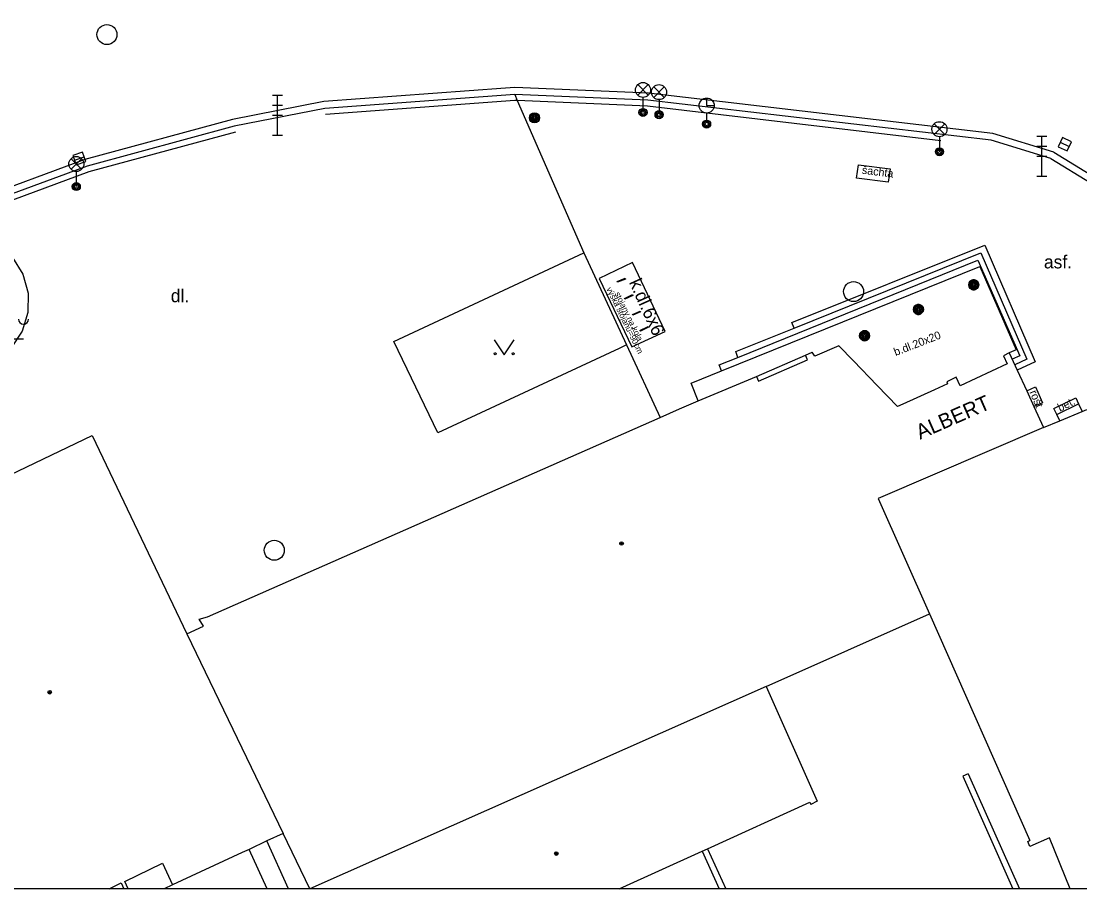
# Model space of a CAD drawing. Extents: x -600309 to -598967, y -1161267 to -1160292.
# Drawn here: x -599307.7 to -599254.8, y -1161267 to -1161223.7 of the extents above; entities that cross this region are included whole.
import ezdxf

# ---------------------------------------------------------------- set-up
doc = ezdxf.new("R2010")
doc.units = 0
for name, color, linetype in [('Level 10', 7, 'Continuous'), ('Level 11', 7, 'Continuous'), ('Level 24', 7, 'Continuous'), ('Level 25', 7, 'Continuous'), ('Level 26', 7, 'Continuous'), ('Level 27', 7, 'Continuous'), ('Level 33', 7, 'Continuous'), ('Level 36', 7, 'Continuous'), ('Level 39', 7, 'Continuous'), ('Level 40', 7, 'Continuous'), ('Level 41', 7, 'Continuous'), ('Level 42', 7, 'Continuous'), ('Level 5', 7, 'Continuous'), ('Level 6', 7, 'Continuous'), ('Level 7', 7, 'Continuous'), ('Level 9', 7, 'Continuous'), ('Vrstva 63', 7, 'Continuous')]:
    doc.layers.add(name, color=color, linetype=linetype)

msp = doc.modelspace()

# ---------------------------------------------------------------- linework, layer by layer
at = {"layer": 'Level 10'}
for points in [[(-599283.05, -1161227.35), (-599292.54, -1161228.05), (-599297.06, -1161228.94), (-599304.4099, -1161230.93), (-599309.89, -1161232.95), (-599324.35, -1161239.64)], [(-599256.27, -1161230.55), (-599259.24, -1161229.64), (-599276.4, -1161227.64), (-599283.05, -1161227.35)], [(-599256.27, -1161230.55), (-599254.25, -1161231.78), (-599252.45, -1161233.3), (-599250.9099, -1161235.09), (-599249.6599, -1161237.1)]]:
    msp.add_lwpolyline(points, dxfattribs=at)
at = {"layer": 'Level 11'}
msp.add_line((-599295.4188, -1161267.0314), (-599296.31, -1161265.06), dxfattribs=at)
for points in [[(-599256.11, -1161230.24), (-599259.17, -1161229.3), (-599276.37, -1161227.29), (-599283.05, -1161227), (-599283.5165, -1161227.0342), (-599292.59, -1161227.7), (-599297.14, -1161228.6), (-599304.52, -1161230.6), (-599310.02, -1161232.63), (-599324.5, -1161239.32), (-599330.9699, -1161242.33), (-599342.09, -1161247.58)], [(-599283.05, -1161227.35), (-599282.92, -1161227.6599)], [(-599282.92, -1161227.6599), (-599279.59, -1161235.27)], [(-599256.11, -1161230.24), (-599254.05, -1161231.5), (-599252.2, -1161233.06), (-599250.62, -1161234.89), (-599249.35, -1161236.94)], [(-599310.7, -1161234.25), (-599309.74, -1161234.4099), (-599308.86, -1161234.84), (-599308.13, -1161235.5), (-599307.62, -1161236.33), (-599307.36, -1161237.27), (-599307.37, -1161238.25), (-599307.6599, -1161239.18), (-599308.2, -1161240)], [(-599269.09, -1161239.02), (-599269.2, -1161238.74), (-599259.57, -1161234.88), (-599257.04, -1161240.71), (-599257.94, -1161241.12)], [(-599289.09, -1161239.69), (-599279.59, -1161235.27)], [(-599279.59, -1161235.27), (-599277.46, -1161239.86)], [(-599269.09, -1161239.02), (-599259.77, -1161235.26), (-599257.46, -1161240.58), (-599258.06, -1161240.86)], [(-599277.17, -1161235.75), (-599278.83, -1161236.54)], [(-599275.53, -1161239.19), (-599277.17, -1161235.75)], [(-599271.9099, -1161240.49), (-599259.9099, -1161235.63), (-599257.82, -1161240.4099), (-599258.19, -1161240.58)], [(-599278.83, -1161236.54), (-599277.19, -1161239.95)], [(-599277.19, -1161239.95), (-599275.53, -1161239.19)], [(-599271.9099, -1161240.49), (-599272, -1161240.19), (-599269.09, -1161239.02)], [(-599277.46, -1161239.86), (-599277.8346, -1161240.0344), (-599286.89, -1161244.25), (-599289.09, -1161239.69)], [(-599277.46, -1161239.86), (-599275.78, -1161243.48)], [(-599272.71, -1161241.1599), (-599272.84, -1161240.86), (-599271.9099, -1161240.49)], [(-599270.9699, -1161241.44), (-599268.52, -1161240.38)], [(-599257.4699, -1161242.15), (-599257.03, -1161241.95), (-599256.69, -1161242.75), (-599257.11, -1161242.94)], [(-599256.11, -1161243.04), (-599255.02, -1161242.51)], [(-599255.97, -1161243.33), (-599254.88, -1161242.8)], [(-599255.02, -1161242.51), (-599254.88, -1161242.8), (-599254.7, -1161243.18)], [(-599255.82, -1161243.65), (-599255.97, -1161243.33), (-599256.11, -1161243.04)], [(-599260.39, -1161261.29), (-599260.6599, -1161261.4099)]]:
    msp.add_lwpolyline(points, dxfattribs=at)
at = {"layer": 'Level 24'}
msp.add_line((-599307.59, -1161239.57), (-599308.09, -1161239.57), dxfattribs=at)
msp.add_arc((-599307.59, -1161238.57), 0.25, 180, 0, dxfattribs=at)
at = {"layer": 'Level 25'}
for points in [[(-599277.91, -1161236.73), (-599277.93, -1161236.69), (-599277.53, -1161236.53)], [(-599277.53, -1161236.53), (-599277.51, -1161236.57), (-599277.91, -1161236.73)], [(-599277.54, -1161237.58), (-599277.56, -1161237.54), (-599277.16, -1161237.35)], [(-599277.16, -1161237.35), (-599277.14, -1161237.39), (-599277.54, -1161237.58)], [(-599277.15, -1161238.38), (-599277.17, -1161238.34), (-599276.78, -1161238.17)], [(-599276.78, -1161238.17), (-599276.76, -1161238.21), (-599277.15, -1161238.38)], [(-599276.77, -1161239.18), (-599276.79, -1161239.14), (-599276.39, -1161238.94)], [(-599276.39, -1161238.94), (-599276.37, -1161238.98), (-599276.77, -1161239.18)]]:
    msp.add_lwpolyline(points, dxfattribs=at)
for centre, radius in [((-599282.06, -1161228.52), 0.25), ((-599282.06, -1161228.52), 0.2), ((-599282.06, -1161228.52), 0.15), ((-599282.06, -1161228.52), 0.1), ((-599282.06, -1161228.52), 0.05), ((-599260.12, -1161236.86), 0.25), ((-599260.12, -1161236.86), 0.2), ((-599260.12, -1161236.86), 0.15), ((-599260.12, -1161236.86), 0.1), ((-599260.12, -1161236.86), 0.05), ((-599262.88, -1161238.09), 0.25), ((-599262.88, -1161238.09), 0.2), ((-599262.88, -1161238.09), 0.15), ((-599262.88, -1161238.09), 0.1), ((-599262.88, -1161238.09), 0.05), ((-599265.57, -1161239.4), 0.25), ((-599265.57, -1161239.4), 0.2), ((-599265.57, -1161239.4), 0.15), ((-599265.57, -1161239.4), 0.1), ((-599265.57, -1161239.4), 0.05)]:
    msp.add_circle(centre, radius, dxfattribs=at)
at = {"layer": 'Level 26'}
msp.add_lwpolyline([(-599264.3, -1161231.07), (-599264.39, -1161231.74), (-599265.97, -1161231.54), (-599265.88, -1161230.87), (-599264.3, -1161231.07)], dxfattribs=at)
at = {"layer": 'Level 27'}
for p, q in [((-599255.7961, -1161229.7333), (-599255.3439, -1161229.9467)), ((-599305.0364, -1161230.6314), (-599304.5636, -1161230.4686))]:
    msp.add_line(p, q, dxfattribs=at)
for points in [[(-599255.9028, -1161229.9594), (-599255.4506, -1161230.1728), (-599255.2372, -1161229.7206), (-599255.6894, -1161229.5072)], [(-599304.955, -1161230.8678), (-599304.4822, -1161230.705), (-599304.645, -1161230.2322), (-599305.1178, -1161230.395)]]:
    msp.add_lwpolyline(points, close=True, dxfattribs=at)
for centre in [(-599303.42, -1161224.36), (-599266.12, -1161237.2), (-599295.06, -1161250.12)]:
    msp.add_circle(centre, 0.5, dxfattribs=at)
at = {"layer": 'Level 33'}
for p, q in [((-599276.905, -1161227.39), (-599276.375, -1161226.86)), ((-599276.905, -1161226.86), (-599276.375, -1161227.39)), ((-599276.105, -1161227.5), (-599275.575, -1161226.97)), ((-599276.105, -1161226.97), (-599275.575, -1161227.5)), ((-599295.15, -1161227.39), (-599294.65, -1161227.39)), ((-599294.9, -1161229.39), (-599294.9, -1161227.39)), ((-599276.64, -1161227.5), (-599276.64, -1161228.25)), ((-599295.15, -1161227.89), (-599294.65, -1161227.89)), ((-599275.84, -1161227.61), (-599275.84, -1161228.36)), ((-599295.15, -1161228.39), (-599294.65, -1161228.39)), ((-599273.46, -1161228.28), (-599273.46, -1161228.63)), ((-599262.095, -1161229.35), (-599261.565, -1161228.82)), ((-599262.095, -1161228.82), (-599261.565, -1161229.35)), ((-599295.15, -1161229.39), (-599294.65, -1161229.39)), ((-599261.83, -1161229.46), (-599261.83, -1161230.21)), ((-599256.96, -1161229.44), (-599256.46, -1161229.44)), ((-599256.71, -1161231.44), (-599256.71, -1161229.44)), ((-599256.96, -1161229.94), (-599256.46, -1161229.94)), ((-599305.215, -1161231.09), (-599304.685, -1161230.56)), ((-599305.215, -1161230.56), (-599304.685, -1161231.09)), ((-599256.96, -1161230.44), (-599256.46, -1161230.44)), ((-599304.95, -1161231.2), (-599304.95, -1161231.95)), ((-599256.96, -1161231.44), (-599256.46, -1161231.44))]:
    msp.add_line(p, q, dxfattribs=at)
msp.add_lwpolyline([(-599273.46, -1161227.53), (-599273.46, -1161227.905), (-599273.085, -1161227.905)], dxfattribs=at)
for centre, radius in [((-599276.64, -1161227.125), 0.375), ((-599275.84, -1161227.235), 0.375), ((-599273.46, -1161227.905), 0.375), ((-599276.64, -1161228.25), 0.2), ((-599276.64, -1161228.25), 0.1445), ((-599276.64, -1161228.25), 0.0876), ((-599275.84, -1161228.36), 0.2), ((-599275.84, -1161228.36), 0.1445), ((-599275.84, -1161228.36), 0.0876), ((-599273.46, -1161228.83), 0.2), ((-599273.46, -1161228.83), 0.1445), ((-599273.46, -1161228.83), 0.0876), ((-599261.83, -1161229.085), 0.375), ((-599261.83, -1161230.21), 0.2), ((-599261.83, -1161230.21), 0.1445), ((-599261.83, -1161230.21), 0.0876), ((-599304.95, -1161230.825), 0.375), ((-599304.95, -1161231.95), 0.2), ((-599304.95, -1161231.95), 0.1445), ((-599304.95, -1161231.95), 0.0876)]:
    msp.add_circle(centre, radius, dxfattribs=at)
at = {"layer": 'Level 36'}
msp.add_lwpolyline([(-599284.07, -1161239.6), (-599283.57, -1161240.35), (-599283.07, -1161239.6)], dxfattribs=at)
for centre in [(-599284.0202, -1161240.2998), (-599283.1208, -1161240.2998)]:
    msp.add_circle(centre, 0.05, dxfattribs=at)
at = {"layer": 'Level 39'}
for centre, radius in [((-599277.71, -1161249.78), 0.09), ((-599277.71, -1161249.78), 0.0398), ((-599306.28, -1161257.21), 0.09), ((-599306.28, -1161257.21), 0.0398), ((-599280.9699, -1161265.27), 0.09), ((-599280.9699, -1161265.27), 0.0398)]:
    msp.add_circle(centre, radius, dxfattribs=at)
at = {"layer": 'Level 5'}
for p, q in [((-599255.3049, -1161267.0314), (-599256.34, -1161264.49)), ((-599294.3582, -1161267.0314), (-599295.44, -1161264.64)), ((-599277.8226, -1161267.0314), (-599273.69, -1161265.15)), ((-599303.3152, -1161267.0314), (-599302.71, -1161266.74)), ((-599302.71, -1161266.74), (-599302.5737, -1161267.0314)), ((-599302.3546, -1161267.0314), (-599302.53, -1161266.6599)), ((-599300.14, -1161266.83), (-599300.5561, -1161267.0314))]:
    msp.add_line(p, q, dxfattribs=at)
for points in [[(-599272.71, -1161241.1599), (-599259.82, -1161235.94)], [(-599259.82, -1161235.94), (-599258, -1161240.1)], [(-599259.87, -1161236.86), (-599259.8738, -1161236.8166), (-599259.8851, -1161236.7745), (-599259.9035, -1161236.735), (-599259.9285, -1161236.6993), (-599259.9593, -1161236.6685), (-599259.995, -1161236.6435), (-599260.0345, -1161236.6251), (-599260.0766, -1161236.6138), (-599260.12, -1161236.61), (-599260.1634, -1161236.6138), (-599260.2055, -1161236.6251), (-599260.245, -1161236.6435), (-599260.2807, -1161236.6685), (-599260.3115, -1161236.6993), (-599260.3365, -1161236.735), (-599260.3549, -1161236.7745), (-599260.3662, -1161236.8166), (-599260.37, -1161236.86), (-599260.3662, -1161236.9034), (-599260.3549, -1161236.9455), (-599260.3365, -1161236.985), (-599260.3115, -1161237.0207), (-599260.2807, -1161237.0515), (-599260.245, -1161237.0765), (-599260.2055, -1161237.0949), (-599260.1634, -1161237.1062), (-599260.12, -1161237.11), (-599260.0766, -1161237.1062), (-599260.0345, -1161237.0949), (-599259.995, -1161237.0765), (-599259.9593, -1161237.0515), (-599259.9285, -1161237.0207), (-599259.9035, -1161236.985), (-599259.8851, -1161236.9455), (-599259.8738, -1161236.9034), (-599259.87, -1161236.86)], [(-599262.63, -1161238.09), (-599262.6338, -1161238.0466), (-599262.6451, -1161238.0045), (-599262.6635, -1161237.965), (-599262.6885, -1161237.9293), (-599262.7193, -1161237.8985), (-599262.755, -1161237.8735), (-599262.7945, -1161237.8551), (-599262.8366, -1161237.8438), (-599262.88, -1161237.84), (-599262.9234, -1161237.8438), (-599262.9655, -1161237.8551), (-599263.005, -1161237.8735), (-599263.0407, -1161237.8985), (-599263.0715, -1161237.9293), (-599263.0965, -1161237.965), (-599263.1149, -1161238.0045), (-599263.1262, -1161238.0466), (-599263.13, -1161238.09), (-599263.1262, -1161238.1334), (-599263.1149, -1161238.1755), (-599263.0965, -1161238.215), (-599263.0715, -1161238.2507), (-599263.0407, -1161238.2815), (-599263.005, -1161238.3065), (-599262.9655, -1161238.3249), (-599262.9234, -1161238.3362), (-599262.88, -1161238.34), (-599262.8366, -1161238.3362), (-599262.7945, -1161238.3249), (-599262.755, -1161238.3065), (-599262.7193, -1161238.2815), (-599262.6885, -1161238.2507), (-599262.6635, -1161238.215), (-599262.6451, -1161238.1755), (-599262.6338, -1161238.1334), (-599262.63, -1161238.09)], [(-599265.32, -1161239.4), (-599265.3238, -1161239.3566), (-599265.3351, -1161239.3145), (-599265.3535, -1161239.275), (-599265.3785, -1161239.2393), (-599265.4093, -1161239.2085), (-599265.445, -1161239.1835), (-599265.4845, -1161239.1651), (-599265.5266, -1161239.1538), (-599265.57, -1161239.15), (-599265.6134, -1161239.1538), (-599265.6555, -1161239.1651), (-599265.695, -1161239.1835), (-599265.7307, -1161239.2085), (-599265.7615, -1161239.2393), (-599265.7865, -1161239.275), (-599265.8049, -1161239.3145), (-599265.8162, -1161239.3566), (-599265.82, -1161239.4), (-599265.8162, -1161239.4434), (-599265.8049, -1161239.4855), (-599265.7865, -1161239.525), (-599265.7615, -1161239.5607), (-599265.7307, -1161239.5915), (-599265.695, -1161239.6165), (-599265.6555, -1161239.6349), (-599265.6134, -1161239.6462), (-599265.57, -1161239.65), (-599265.5266, -1161239.6462), (-599265.4845, -1161239.6349), (-599265.445, -1161239.6165), (-599265.4093, -1161239.5915), (-599265.3785, -1161239.5607), (-599265.3535, -1161239.525), (-599265.3351, -1161239.4855), (-599265.3238, -1161239.4434), (-599265.32, -1161239.4)], [(-599268.52, -1161240.38), (-599268.19, -1161240.2199)], [(-599268.05, -1161240.42), (-599268.19, -1161240.2199)], [(-599266.85, -1161239.9), (-599268.05, -1161240.42)], [(-599266.13, -1161240.65), (-599266.85, -1161239.9)], [(-599258.34, -1161240.25), (-599258.63, -1161240.4)], [(-599258, -1161240.1), (-599258.34, -1161240.25)], [(-599258.34, -1161240.25), (-599257.94, -1161241.12)], [(-599270.87, -1161241.67), (-599268.42, -1161240.61)], [(-599268.42, -1161240.61), (-599268.52, -1161240.38)], [(-599264.94, -1161241.89), (-599266.13, -1161240.65)], [(-599258.44, -1161240.81), (-599260.8, -1161241.9)], [(-599258.63, -1161240.4), (-599258.44, -1161240.81)], [(-599274.24, -1161241.78), (-599272.71, -1161241.1599)], [(-599257.94, -1161241.12), (-599257.4699, -1161242.15)], [(-599273.89, -1161242.65), (-599274.24, -1161241.78)], [(-599273.89, -1161242.65), (-599270.9699, -1161241.44)], [(-599270.9699, -1161241.44), (-599270.87, -1161241.67)], [(-599261.42, -1161241.8), (-599262.08, -1161242.1)], [(-599260.99, -1161241.48), (-599261.46, -1161241.7)], [(-599261.46, -1161241.7), (-599261.42, -1161241.8)], [(-599260.8, -1161241.9), (-599260.99, -1161241.48)], [(-599263.93, -1161242.94), (-599264.94, -1161241.89)], [(-599262.08, -1161242.1), (-599263.6599, -1161242.82)], [(-599257.4699, -1161242.15), (-599257.11, -1161242.94)], [(-599275.78, -1161243.48), (-599274.8206, -1161243.0587), (-599273.89, -1161242.65)], [(-599263.6599, -1161242.82), (-599263.93, -1161242.94)], [(-599257.11, -1161242.94), (-599256.63, -1161243.98)], [(-599256.63, -1161243.98), (-599255.82, -1161243.65), (-599254.7, -1161243.18), (-599254.4699, -1161243.09)], [(-599298.39, -1161253.44), (-599276.1995, -1161243.6648), (-599275.78, -1161243.48)], [(-599256.63, -1161243.98), (-599264.89, -1161247.54)], [(-599309.49, -1161246.94), (-599304.1599, -1161244.39)], [(-599304.1599, -1161244.39), (-599299.43, -1161254.3)], [(-599264.89, -1161247.54), (-599262.33, -1161253.3)], [(-599298.81, -1161253.56), (-599298.39, -1161253.44)], [(-599270.49, -1161256.92), (-599262.33, -1161253.3)], [(-599262.33, -1161253.3), (-599257.31, -1161264.61)], [(-599299.43, -1161254.3), (-599298.59, -1161253.9099)], [(-599298.59, -1161253.9099), (-599298.81, -1161253.56)], [(-599299.43, -1161254.3), (-599294.62, -1161264.27)], [(-599270.49, -1161256.92), (-599293.29, -1161267.03)], [(-599270.49, -1161256.92), (-599267.94, -1161262.65)], [(-599273.42, -1161265.03), (-599268.31, -1161262.7)], [(-599268.31, -1161262.7), (-599268.26, -1161262.82)], [(-599267.94, -1161262.65), (-599268.26, -1161262.82)], [(-599294.62, -1161264.27), (-599295.44, -1161264.64)], [(-599293.29, -1161267.03), (-599294.62, -1161264.27)], [(-599257.42, -1161264.6599), (-599257.31, -1161264.61)], [(-599256.34, -1161264.49), (-599257.31, -1161264.92)], [(-599296.31, -1161265.06), (-599296.6599, -1161265.2199)], [(-599295.44, -1161264.64), (-599296.31, -1161265.06)], [(-599273.69, -1161265.15), (-599273.42, -1161265.03)], [(-599257.31, -1161264.92), (-599257.42, -1161264.6599)], [(-599296.6599, -1161265.2199), (-599300.14, -1161266.83)], [(-599302.53, -1161266.6599), (-599300.65, -1161265.75)], [(-599300.65, -1161265.75), (-599300.14, -1161266.83)]]:
    msp.add_lwpolyline(points, dxfattribs=at)
at = {"layer": 'Level 6'}
for points in [[(-599264.94, -1161241.89), (-599266.13, -1161240.65)], [(-599262.08, -1161242.1), (-599263.6599, -1161242.82)]]:
    msp.add_lwpolyline(points, dxfattribs=at)
at = {"layer": 'Level 7'}
for p, q in [((-599260.6599, -1161261.4099), (-599258.1658, -1161267.0314)), ((-599260.39, -1161261.29), (-599257.8365, -1161267.0314)), ((-599273.69, -1161265.15), (-599272.8382, -1161267.0314)), ((-599273.42, -1161265.03), (-599272.5083, -1161267.0314))]:
    msp.add_line(p, q, dxfattribs=at)
at = {"layer": 'Level 9'}
for points in [[(-599282.92, -1161227.6599), (-599283.04, -1161227.65), (-599292.5, -1161228.35)], [(-599261.76, -1161229.6599), (-599276.42, -1161227.94), (-599282.92, -1161227.6599)], [(-599296.99, -1161229.23), (-599304.32, -1161231.2199), (-599309.77, -1161233.23)]]:
    msp.add_lwpolyline(points, dxfattribs=at)
at = {"layer": 'Vrstva 63'}
msp.add_lwpolyline([(-600308.541, -1160292.3474), (-598967.1085, -1160292.3474), (-598967.1085, -1161267.0314), (-600308.541, -1161267.0314)], close=True, dxfattribs=at)

# ---------------------------------------------------------------- texts
at = {"layer": 'Level 40'}
for s, p in [('asf.', (-599256.61, -1161236.04)), ('dl.', (-599300.23, -1161237.73))]:
    msp.add_text(s, height=0.65, dxfattribs=at).set_placement(p)
for s, height, rotation, p in [('k.dl.6x6', 0.65, 294.20636, (-599277.35, -1161236.73)), ('b.dl.20x20', 0.4, 21.28263, (-599264.02, -1161240.42)), ('bet.', 0.4, 26, (-599255.81, -1161243.2))]:
    msp.add_text(s, height=height, rotation=rotation, dxfattribs=at).set_placement(p)
at = {"layer": 'Level 41'}
msp.add_text('ALBERT', height=0.75, rotation=23.72275, dxfattribs=at).set_placement((-599262.8, -1161244.6))
at = {"layer": 'Level 42'}
for s, height, rotation, p in [('šachta', 0.4, 353, (-599265.72, -1161231.31)), ('výška stojanů=90cm', 0.3, 296, (-599278.48, -1161237.06)), ('stojany na kola', 0.3, 296, (-599278.07, -1161237.3)), ('rošt', 0.4, 292.92056, (-599257.34, -1161242.22))]:
    msp.add_text(s, height=height, rotation=rotation, dxfattribs=at).set_placement(p)

doc.saveas('drawing.dxf')
